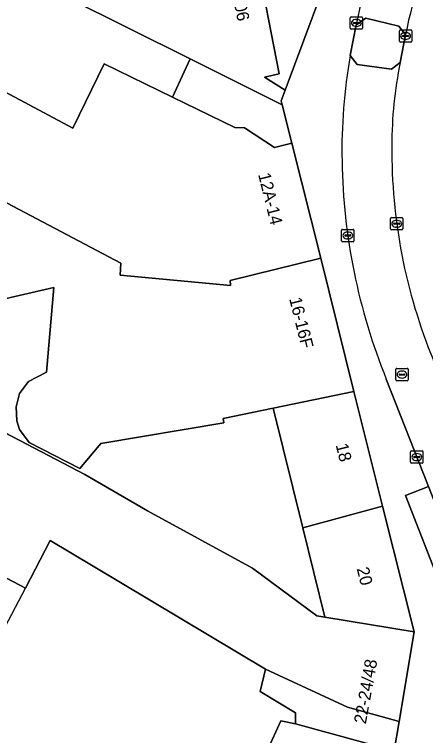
# Model space of a CAD drawing. Extents: x 160663 to 161506, y 382245 to 383291.
# Drawn here: x 161096.2 to 161129.6, y 383126.7 to 383185.2 of the extents above; entities that cross this region are included whole.
import ezdxf

# ---------------------------------------------------------------- set-up
doc = ezdxf.new("R2010")
doc.units = 0
for name, color, linetype in [('IMGEO_Erf', 7, 'Continuous'), ('IMGEO_Kolk', 7, 'Continuous'), ('IMGEO_Pand', 7, 'Continuous'), ('IMGEO_Pand_nummerreeks', 7, 'Continuous'), ('IMGEO_Pand_overbouw', 7, 'Continuous'), ('IMGEO_Parkeervlak_open', 7, 'Continuous'), ('IMGEO_Rijbaan_lokaal_open', 7, 'Continuous'), ('IMGEO_Rioolput', 7, 'Continuous'), ('IMGEO_Voetpad_open', 7, 'Continuous'), ('IMGEO_Woonerf_open', 7, 'Continuous')]:
    doc.layers.add(name, color=color, linetype=linetype)

msp = doc.modelspace()

# ---------------------------------------------------------------- linework, layer by layer
at = {"layer": 'IMGEO_Erf'}
for points in [[(161081.255, 383186.535), (161100.959, 383175.995), (161103.503, 383181.205), (161109.057, 383178.493), (161110.478, 383181.608), (161095.547, 383189.071)], [(161093.072, 383152.528), (161101.931, 383147.903), (161107.028, 383144.962), (161115.538, 383140.311), (161120.748, 383136.427), (161121.403, 383136.321), (161119.609, 383143.566), (161117.202, 383153.285), (161113.148, 383152.452), (161113.208, 383152.083), (161103.248, 383150.412), (161101.528, 383148.392), (161097.433, 383150.492), (161096.639, 383151.554), (161096.423, 383152.245), (161096.364, 383153.385), (161096.655, 383154.472), (161097.384, 383155.445), (161098.84, 383156.201), (161099.42, 383163.067), (161091.306, 383161.202)], [(161089.879, 383113.891), (161102.23, 383107.686), (161104.228, 383111.663), (161097.042, 383115.272), (161099.825, 383120.963), (161106.266, 383118.007), (161108.894, 383116.654), (161108.95, 383116.775), (161111.345, 383121.996), (161111.915, 383121.735), (161113.061, 383124.233), (161115.611, 383123.064), (161117.845, 383127.933), (161119.014, 383127.673), (161119.028, 383128.579), (161116.147, 383130.304), (161116.598, 383132.104), (161102.611, 383140.477), (161099.139, 383142.555), (161097.125, 383138.696), (161093.57, 383140.552)]]:
    msp.add_lwpolyline(points, dxfattribs=at)
at = {"layer": 'IMGEO_Kolk'}
for p, q in [((161123.541, 383185.015), (161124.393, 383185.015)), ((161123.466, 383184.089), (161123.466, 383184.941)), ((161123.725, 383184.509), (161123.725, 383184.521)), ((161124.163, 383184.472), (161123.765, 383184.472)), ((161123.768, 383184.558), (161124.166, 383184.558)), ((161123.954, 383184.795), (161123.979, 383184.795)), ((161124.209, 383184.521), (161124.209, 383184.509)), ((161124.467, 383184.941), (161124.467, 383184.089)), ((161124.393, 383184.015), (161123.541, 383184.015)), ((161123.977, 383184.235), (161123.952, 383184.235)), ((161127.453, 383183.031), (161127.453, 383183.883)), ((161127.528, 383183.957), (161128.38, 383183.957)), ((161128.454, 383183.883), (161128.454, 383183.031)), ((161127.712, 383183.451), (161127.712, 383183.463)), ((161128.15, 383183.414), (161127.752, 383183.414)), ((161127.755, 383183.5), (161128.153, 383183.5)), ((161127.941, 383183.737), (161127.966, 383183.737)), ((161128.196, 383183.463), (161128.196, 383183.451)), ((161128.38, 383182.957), (161127.528, 383182.957)), ((161127.964, 383183.177), (161127.939, 383183.177)), ((161126.736, 383167.81), (161126.736, 383168.662)), ((161126.811, 383168.736), (161127.663, 383168.736)), ((161127.737, 383168.662), (161127.737, 383167.81)), ((161126.995, 383168.23), (161126.995, 383168.242)), ((161127.433, 383168.193), (161127.035, 383168.193)), ((161127.038, 383168.279), (161127.436, 383168.279)), ((161127.224, 383168.516), (161127.249, 383168.516)), ((161127.479, 383168.242), (161127.479, 383168.23)), ((161122.765, 383166.853), (161122.765, 383167.705)), ((161122.84, 383167.779), (161123.692, 383167.779)), ((161123.253, 383167.559), (161123.278, 383167.559)), ((161123.766, 383167.705), (161123.766, 383166.853)), ((161127.663, 383167.736), (161126.811, 383167.736)), ((161127.247, 383167.956), (161127.222, 383167.956)), ((161123.024, 383167.273), (161123.024, 383167.285)), ((161123.462, 383167.236), (161123.064, 383167.236)), ((161123.067, 383167.322), (161123.465, 383167.322)), ((161123.276, 383166.999), (161123.251, 383166.999)), ((161123.508, 383167.285), (161123.508, 383167.273)), ((161123.692, 383166.779), (161122.84, 383166.779)), ((161128.364, 383148.891), (161128.364, 383149.743)), ((161128.439, 383149.817), (161129.291, 383149.817)), ((161128.623, 383149.311), (161128.623, 383149.323)), ((161128.666, 383149.36), (161129.064, 383149.36)), ((161128.852, 383149.597), (161128.877, 383149.597)), ((161129.107, 383149.323), (161129.107, 383149.311)), ((161129.365, 383149.743), (161129.365, 383148.891)), ((161129.291, 383148.817), (161128.439, 383148.817)), ((161129.061, 383149.274), (161128.663, 383149.274)), ((161128.875, 383149.037), (161128.85, 383149.037))]:
    msp.add_line(p, q, dxfattribs=at)
for points in [[(161123.541, 383185.015), (161124.393, 383185.015)], [(161123.466, 383184.089), (161123.466, 383184.941)], [(161124.467, 383184.941), (161124.467, 383184.089)], [(161124.393, 383184.015), (161123.541, 383184.015)], [(161127.453, 383183.031), (161127.453, 383183.883)], [(161127.528, 383183.957), (161128.38, 383183.957)], [(161128.454, 383183.883), (161128.454, 383183.031)], [(161128.38, 383182.957), (161127.528, 383182.957)], [(161126.736, 383167.81), (161126.736, 383168.662)], [(161126.811, 383168.736), (161127.663, 383168.736)], [(161127.737, 383168.662), (161127.737, 383167.81)], [(161122.765, 383166.853), (161122.765, 383167.705)], [(161122.84, 383167.779), (161123.692, 383167.779)], [(161123.766, 383167.705), (161123.766, 383166.853)], [(161127.663, 383167.736), (161126.811, 383167.736)], [(161123.692, 383166.779), (161122.84, 383166.779)], [(161128.364, 383148.891), (161128.364, 383149.743)], [(161128.439, 383149.817), (161129.291, 383149.817)], [(161129.365, 383149.743), (161129.365, 383148.891)], [(161129.291, 383148.817), (161128.439, 383148.817)]]:
    msp.add_lwpolyline(points, dxfattribs=at)
for centre, radius, start, end in [((161123.543, 383184.939), 0.0765, 91.55205, 178.44795), ((161123.543, 383184.939), 0.0765, 91.55205, 178.44795), ((161124.391, 383184.939), 0.0765, 1.55205, 88.44795), ((161124.391, 383184.939), 0.0765, 1.55205, 88.44795), ((161123.765, 383184.518), 0.0403, 85.87752, 175.75265), ((161123.762, 383184.508), 0.0366, 178.93798, 274.71019), ((161124.166, 383184.515), 0.043, 264.86636, 352.45326), ((161124.17, 383184.52), 0.0386, 1.73085, 96.63898), ((161123.543, 383184.091), 0.0765, 181.55205, 268.44795), ((161123.543, 383184.091), 0.0765, 181.55205, 268.44795), ((161124.391, 383184.091), 0.0765, 271.55205, 358.44795), ((161124.391, 383184.091), 0.0765, 271.55205, 358.44795), ((161127.53, 383183.881), 0.0765, 91.55205, 178.44795), ((161127.53, 383183.881), 0.0765, 91.55205, 178.44795), ((161128.378, 383183.881), 0.0765, 1.55205, 88.44795), ((161128.378, 383183.881), 0.0765, 1.55205, 88.44795), ((161127.752, 383183.46), 0.0403, 85.87752, 175.75265), ((161127.749, 383183.45), 0.0366, 178.93798, 274.71019), ((161128.153, 383183.457), 0.043, 264.86636, 352.45326), ((161128.157, 383183.462), 0.0386, 1.73085, 96.63898), ((161127.53, 383183.033), 0.0765, 181.55205, 268.44795), ((161127.53, 383183.033), 0.0765, 181.55205, 268.44795), ((161128.378, 383183.033), 0.0765, 271.55205, 358.44795), ((161128.378, 383183.033), 0.0765, 271.55205, 358.44795), ((161126.813, 383168.66), 0.0765, 91.55205, 178.44795), ((161126.813, 383168.66), 0.0765, 91.55205, 178.44795), ((161127.661, 383168.66), 0.0765, 1.55205, 88.44795), ((161127.661, 383168.66), 0.0765, 1.55205, 88.44795), ((161127.035, 383168.239), 0.0403, 85.87752, 175.75265), ((161127.032, 383168.229), 0.0366, 178.93798, 274.71019), ((161127.436, 383168.236), 0.043, 264.86636, 352.45326), ((161127.44, 383168.241), 0.0386, 1.73085, 96.63898), ((161122.842, 383167.703), 0.0765, 91.55205, 178.44795), ((161122.842, 383167.703), 0.0765, 91.55205, 178.44795), ((161123.69, 383167.703), 0.0765, 1.55205, 88.44795), ((161123.69, 383167.703), 0.0765, 1.55205, 88.44795), ((161126.813, 383167.812), 0.0765, 181.55205, 268.44795), ((161126.813, 383167.812), 0.0765, 181.55205, 268.44795), ((161127.661, 383167.812), 0.0765, 271.55205, 358.44795), ((161127.661, 383167.812), 0.0765, 271.55205, 358.44795), ((161123.064, 383167.282), 0.0403, 85.87752, 175.75265), ((161123.061, 383167.272), 0.0366, 178.93798, 274.71019), ((161123.465, 383167.279), 0.043, 264.86636, 352.45326), ((161123.469, 383167.284), 0.0386, 1.73085, 96.63898), ((161122.842, 383166.855), 0.0765, 181.55205, 268.44795), ((161122.842, 383166.855), 0.0765, 181.55205, 268.44795), ((161123.69, 383166.855), 0.0765, 271.55205, 358.44795), ((161123.69, 383166.855), 0.0765, 271.55205, 358.44795), ((161128.441, 383149.741), 0.0765, 91.55205, 178.44795), ((161128.441, 383149.741), 0.0765, 91.55205, 178.44795), ((161128.663, 383149.32), 0.0403, 85.87752, 175.75265), ((161129.068, 383149.322), 0.0386, 1.73085, 96.63898), ((161129.289, 383149.741), 0.0765, 1.55205, 88.44795), ((161129.289, 383149.741), 0.0765, 1.55205, 88.44795), ((161128.441, 383148.893), 0.0765, 181.55205, 268.44795), ((161128.441, 383148.893), 0.0765, 181.55205, 268.44795), ((161128.66, 383149.31), 0.0366, 178.93798, 274.71019), ((161129.064, 383149.317), 0.043, 264.86636, 352.45326), ((161129.289, 383148.893), 0.0765, 271.55205, 358.44795), ((161129.289, 383148.893), 0.0765, 271.55205, 358.44795)]:
    msp.add_arc(centre, radius, start, end, dxfattribs=at)
for centre, major_axis, ratio, start_param, end_param in [((161123.953, 383184.515), (-0.387, 0.002), 0.722429, 4.712389, 7.853982), ((161123.978, 383184.515), (-0.39, 0.002), 0.717154, 1.570796, 4.712389), ((161127.94, 383183.457), (-0.387, 0.002), 0.722429, 4.712389, 7.853982), ((161127.965, 383183.457), (-0.39, 0.002), 0.717154, 1.570796, 4.712389), ((161127.223, 383168.236), (-0.387, 0.002), 0.722429, 4.712389, 7.853982), ((161127.248, 383168.236), (-0.39, 0.002), 0.717154, 1.570796, 4.712389), ((161123.252, 383167.279), (-0.387, 0.002), 0.722429, 4.712389, 7.853982), ((161123.277, 383167.279), (-0.39, 0.002), 0.717154, 1.570796, 4.712389), ((161128.851, 383149.317), (-0.387, 0.002), 0.722429, 4.712389, 7.853982), ((161128.876, 383149.317), (-0.39, 0.002), 0.717154, 1.570796, 4.712389)]:
    msp.add_ellipse(centre, major_axis=major_axis, ratio=ratio, start_param=start_param, end_param=end_param, dxfattribs=at)
at = {"layer": 'IMGEO_Pand'}
for points in [[(161100.073, 383205.392), (161091.175, 383210.722), (161087.244, 383213.077), (161082.477, 383215.933), (161075.336, 383203.467), (161080.885, 383200.253), (161096.619, 383191.43), (161095.547, 383189.071), (161110.478, 383181.608), (161117.957, 383177.87), (161117.874, 383178.199), (161118.198, 383179.071), (161116.502, 383180.107), (161117.708, 383180.395), (161115.772, 383190.243), (161114.856, 383191.109), (161115.205, 383192.309), (161122.638, 383191.044), (161122.863, 383191.511), (161116.818, 383194.821), (161117.002, 383195.25), (161115.85, 383195.94)], [(161121.067, 383165.435), (161118.733, 383174.765), (161117.328, 383174.414), (161114.888, 383176.008), (161114.107, 383176.028), (161109.057, 383178.493), (161103.503, 383181.205), (161100.959, 383175.995), (161081.255, 383186.535), (161077.562, 383179.631), (161084.173, 383176.029), (161092.19, 383171.7), (161104.857, 383165.031), (161104.797, 383164.068), (161113.763, 383163.235), (161113.717, 383163.628)], [(161123.768, 383154.635), (161117.202, 383153.285), (161119.609, 383143.566), (161126.092, 383145.344)], [(161121.403, 383136.321), (161120.748, 383136.427), (161115.538, 383140.311), (161107.028, 383144.962), (161101.931, 383147.903), (161093.072, 383152.528), (161081.643, 383130.636), (161090.502, 383126.011), (161095.213, 383135.035), (161091.641, 383136.9), (161093.57, 383140.552), (161097.125, 383138.696), (161099.139, 383142.555), (161102.611, 383140.477), (161116.598, 383132.104), (161123.247, 383129.032), (161127.423, 383127.878), (161128.643, 383135.145)], [(161126.092, 383145.344), (161119.609, 383143.566), (161121.403, 383136.321), (161128.643, 383135.145)], [(161126.626, 383125.121), (161126.982, 383125.25), (161127.024, 383125.501), (161119.014, 383127.673), (161117.845, 383127.933), (161115.611, 383123.064), (161113.061, 383124.233), (161111.915, 383121.735), (161111.345, 383121.996), (161108.95, 383116.775), (161108.894, 383116.654), (161111.496, 383115.315), (161111.409, 383115.158), (161120.108, 383110.731)]]:
    msp.add_lwpolyline(points, close=True, dxfattribs=at)
msp.add_lwpolyline([(161091.306, 383161.202), (161099.42, 383163.067), (161098.84, 383156.201), (161097.384, 383155.445), (161096.655, 383154.472), (161096.364, 383153.385), (161096.423, 383152.245), (161096.639, 383151.554), (161097.433, 383150.492), (161101.528, 383148.392), (161103.248, 383150.412), (161113.208, 383152.083), (161113.148, 383152.452), (161117.202, 383153.285), (161123.768, 383154.635), (161121.067, 383165.435), (161113.717, 383163.628), (161113.763, 383163.235), (161104.797, 383164.068), (161104.857, 383165.031), (161092.19, 383171.7)], dxfattribs=at)
at = {"layer": 'IMGEO_Pand_overbouw'}
for points in [[(161122.638, 383191.044), (161115.205, 383192.309), (161114.856, 383191.109), (161115.772, 383190.243), (161117.708, 383180.395), (161116.502, 383180.107), (161118.198, 383179.071)], [(161118.733, 383174.765), (161117.957, 383177.87), (161110.478, 383181.608), (161109.057, 383178.493), (161114.107, 383176.028), (161114.888, 383176.008), (161117.328, 383174.414)], [(161097.125, 383138.696), (161093.57, 383140.552), (161091.641, 383136.9), (161095.213, 383135.035)], [(161127.423, 383127.878), (161123.247, 383129.032), (161116.598, 383132.104), (161116.147, 383130.304), (161119.028, 383128.579), (161119.014, 383127.673), (161127.024, 383125.501)]]:
    msp.add_lwpolyline(points, close=True, dxfattribs=at)
at = {"layer": 'IMGEO_Parkeervlak_open'}
msp.add_lwpolyline([(161129.801, 383146.932), (161127.933, 383146.199), (161133.742, 383131.385), (161135.611, 383132.118), (161135.206, 383133.15), (161134.356, 383135.317)], close=True, dxfattribs=at)
at = {"layer": 'IMGEO_Rijbaan_lokaal_open'}
for points in [[(161117.957, 383177.87), (161110.478, 383181.608), (161109.057, 383178.493), (161114.107, 383176.028), (161114.888, 383176.008), (161117.328, 383174.414), (161118.733, 383174.765)], [(161127.423, 383127.878), (161123.247, 383129.032), (161116.598, 383132.104), (161116.147, 383130.304), (161119.028, 383128.579), (161119.014, 383127.673), (161127.024, 383125.501)]]:
    msp.add_lwpolyline(points, close=True, dxfattribs=at)
at = {"layer": 'IMGEO_Rioolput'}
for p, q in [((161127.162, 383155.578), (161127.162, 383156.43)), ((161127.237, 383156.504), (161128.089, 383156.504)), ((161128.163, 383156.43), (161128.163, 383155.578)), ((161127.421, 383155.998), (161127.421, 383156.01)), ((161127.859, 383155.961), (161127.461, 383155.961)), ((161127.464, 383156.047), (161127.862, 383156.047)), ((161127.65, 383156.284), (161127.675, 383156.284)), ((161127.905, 383156.01), (161127.905, 383155.998)), ((161128.089, 383155.504), (161127.237, 383155.504)), ((161127.673, 383155.724), (161127.648, 383155.724))]:
    msp.add_line(p, q, dxfattribs=at)
for points in [[(161127.162, 383155.578), (161127.162, 383156.43)], [(161127.237, 383156.504), (161128.089, 383156.504)], [(161128.163, 383156.43), (161128.163, 383155.578)], [(161128.089, 383155.504), (161127.237, 383155.504)]]:
    msp.add_lwpolyline(points, dxfattribs=at)
for centre, radius, start, end in [((161127.239, 383156.428), 0.0765, 91.55205, 178.44795), ((161127.239, 383156.428), 0.0765, 91.55205, 178.44795), ((161128.087, 383156.428), 0.0765, 1.55205, 88.44795), ((161128.087, 383156.428), 0.0765, 1.55205, 88.44795), ((161127.461, 383156.007), 0.0403, 85.87752, 175.75265), ((161127.458, 383155.997), 0.0366, 178.93798, 274.71019), ((161127.862, 383156.004), 0.043, 264.86636, 352.45326), ((161127.866, 383156.009), 0.0386, 1.73085, 96.63898), ((161127.239, 383155.58), 0.0765, 181.55205, 268.44795), ((161127.239, 383155.58), 0.0765, 181.55205, 268.44795), ((161128.087, 383155.58), 0.0765, 271.55205, 358.44795), ((161128.087, 383155.58), 0.0765, 271.55205, 358.44795)]:
    msp.add_arc(centre, radius, start, end, dxfattribs=at)
for centre, major_axis, ratio, start_param, end_param in [((161127.649, 383156.004), (-0.387, 0.002), 0.722429, 4.712389, 7.853982), ((161127.674, 383156.004), (-0.39, 0.002), 0.717154, 1.570796, 4.712389)]:
    msp.add_ellipse(centre, major_axis=major_axis, ratio=ratio, start_param=start_param, end_param=end_param, dxfattribs=at)
at = {"layer": 'IMGEO_Voetpad_open'}
msp.add_lwpolyline([(161122.638, 383191.044), (161115.205, 383192.309), (161114.856, 383191.109), (161115.772, 383190.243), (161117.708, 383180.395), (161116.502, 383180.107), (161118.198, 383179.071)], close=True, dxfattribs=at)
for points in [[(161122.638, 383191.044), (161118.198, 383179.071), (161117.874, 383178.199), (161117.957, 383177.87), (161118.733, 383174.765), (161121.067, 383165.435), (161123.768, 383154.635), (161126.092, 383145.344), (161128.643, 383135.145), (161127.423, 383127.878), (161127.024, 383125.501)], [(161123.469, 383181.871), (161123.945, 383184.351)], [(161096.232, 383065.041), (161097.948, 383067.723), (161100.236, 383068.269), (161101.27, 383070.058), (161102.587, 383072.301), (161107.023, 383080.092), (161110.056, 383085.418), (161110.781, 383085.656), (161120.09, 383100.134), (161120.161, 383100.245), (161118.207, 383101.501), (161124.761, 383111.696), (161126.716, 383110.439), (161127.839, 383112.186), (161127.679, 383113.208), (161135.448, 383125.333), (161133.773, 383126.361), (161133.469, 383127.948), (161135.792, 383131.655), (161135.611, 383132.118), (161133.742, 383131.385), (161127.933, 383146.199), (161129.801, 383146.932), (161126.39, 383155.632)]]:
    msp.add_lwpolyline(points, dxfattribs=at)
for centre, radius, start, end in [((161167.542, 383175.962), 44.397, 155.69582, 169.10828), ((161166.306, 383174.201), 43.518, 169.84851, 181.18228), ((161172.053, 383174.117), 49.263, 180.94722, 202.03905)]:
    msp.add_arc(centre, radius, start, end, dxfattribs=at)
at = {"layer": 'IMGEO_Woonerf_open'}
msp.add_lwpolyline([(161127.945, 383183.554), (161127.403, 383184.249), (161124.723, 383184.903), (161123.945, 383184.351), (161123.469, 383181.871), (161124.017, 383181.145), (161126.808, 383180.771), (161127.525, 383181.313)], close=True, dxfattribs=at)
for points in [[(161123.945, 383184.351), (161124.723, 383184.903), (161127.403, 383184.249), (161127.945, 383183.554)], [(161127.945, 383183.554), (161127.525, 383181.313)], [(161127.525, 383181.313), (161126.808, 383180.771), (161124.017, 383181.145), (161123.469, 383181.871)], [(161126.39, 383155.632), (161129.801, 383146.932), (161134.356, 383135.317), (161134.733, 383136.197), (161137.382, 383137.217), (161138.12, 383136.927), (161130.21, 383157.169)]]:
    msp.add_lwpolyline(points, dxfattribs=at)
for centre, radius, start, end in [((161167.542, 383175.962), 44.397, 155.69582, 169.10828), ((161170.895, 383174.782), 43.837, 155.87261, 168.45677), ((161170.895, 383174.782), 43.837, 155.87261, 168.45677), ((161166.306, 383174.201), 43.518, 169.84851, 181.18228), ((161159.123, 383174.706), 32.281, 168.19049, 180.24195), ((161159.123, 383174.706), 32.281, 168.19049, 180.24195), ((161171.449, 383174.177), 44.609, 179.49576, 202.41278), ((161171.449, 383174.177), 44.609, 179.49576, 202.41278), ((161172.053, 383174.117), 49.263, 180.94722, 202.03905)]:
    msp.add_arc(centre, radius, start, end, dxfattribs=at)

# ---------------------------------------------------------------- texts
at = {"layer": 'IMGEO_Pand_nummerreeks'}
for s, rotation, p in [('12-12/06', 281.1209, (161113.316, 383189.776)), ('12A-14', 284.05069, (161115.985, 383172.236)), ('16-16F', 284.04623, (161118.509, 383162.15)), ('18', 284.04299, (161122.277, 383150.295)), ('20', 284.11943, (161123.978, 383140.266)), ('22-24/48', 79.73486, (161124.729, 383127.63))]:
    msp.add_text(s, height=1, rotation=rotation, dxfattribs=at).set_placement(p)

doc.saveas('drawing.dxf')
